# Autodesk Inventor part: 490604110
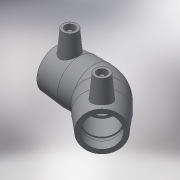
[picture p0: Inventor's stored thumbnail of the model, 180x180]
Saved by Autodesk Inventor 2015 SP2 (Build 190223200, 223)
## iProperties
Created: 2017-06
Part Number: 490604110
Material: Generic
Description: PLASSON 45° ELBOW 110
Document SubType Name: Modeling
Designer: KIM
Mass: 55.0731 g
Surface Area: 148.067 cm^2
Volume: 55.0731 cm^3
Density: 1 g/cm^3
Appearance: Default
Author: KIM
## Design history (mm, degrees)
derived "490604.ipt"
feature "Solid1::490604.ipt"
tag "TaggingFeature1"
body "Solid1"
other parameters: "d2" = 143, "d4" = 67.75, "d5" = 128.7, "d8" = 168 deg, "d10" = 32.4, "d11" = 10.8, "d14" = 17.6296, "d19" = 3.52592, "d20" = 168 deg, "d22" = 131.56, "d23" = 143, "d24" = 127.6132, "d29" = 78, "d30" = 15, "d31" = 94.85, "d34" = 5 deg, "d35" = 12, "d39" = 0, "d41" = 4, "d42" = 14, "d43" = 0, "d44" = 9.6, "d45" = 4.8, "d46" = 6, "d47" = 0, "d50" = 93.5, "d51" = 32.4, "d52" = 81, "d54" = 135 deg, "d67" = 45 deg, "d71" = 135 deg, "d75" = 7.15, "d82" = 45 deg, "d83" = 81, "d84" = 128.7, "d86" = 64.35, "d87" = 135 deg, "d88" = 271, "d90" = 81, "d91" = 0, "d92" = 81, "d93" = 0, "d94" = 135 deg, "d95" = 65.78, "d98" = 271, "d99" = 81.3, "d101" = 3, "d102" = 0, "d103" = 3, "d104" = 0, "d105" = 23.49, "d106" = 5.8725, "L_" = 271, "L_1" = 81, "D_" = 143, "A_" = 78, "d_2" = 12
